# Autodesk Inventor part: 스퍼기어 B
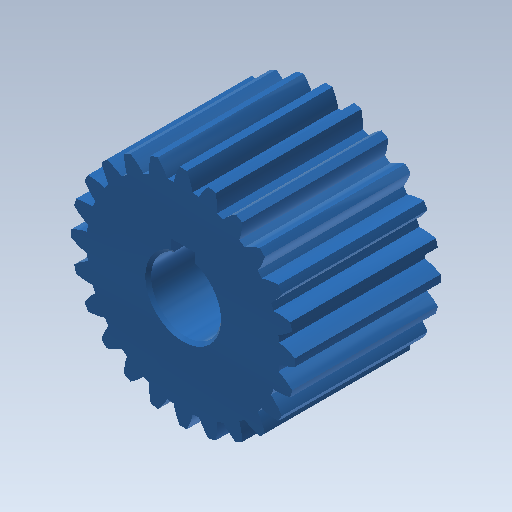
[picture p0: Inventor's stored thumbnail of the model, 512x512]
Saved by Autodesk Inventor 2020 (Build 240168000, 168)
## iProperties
CustomPartVersion: 1
Created: 2020-04
Part Number: 스퍼기어 B
Material: 강철, 연강
Document SubType Name: Modeling
Designer: mduedu
Categories: <?xml version="1.0" encoding="UTF-16"?> <MemberInstance><Categories><FamilyTemplate><FamilyTemplateParameter ValueType="xs:double" Id="1" ObjectReferenceKey="da
Density: 7.86 g/cm^3
Mass: 175.416 g
Surface Area: 76.8935 cm^2
Volume: 22.3176 cm^3
Appearance: 청록색
Author: mduedu
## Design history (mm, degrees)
sketch "Sketch1"
  geometry: C1 r 19.2 at (0, 0)
  constraints: 1 centre point
  dimensions: "d0" = 38.4 diameter of C1 (= da_da)
extrude "Extrusion1" new body sketch "Sketch1" distance "d1" = 25 (= da_b); taper "d2" = 0 deg
workplane "Work Plane2"
sketch "Sketch2"
  geometry: C1 r 19.2 at (0, 0) reference; C2 r 18 at (0, 0)
  constraints: 1 centre point, 1 coincident
  dimensions: "d3" = 36 diameter of C2 (= da_dw)
feature "피치 지름" sketch "Sketch2" dims "d4" = 10, "d5" = 0
workplane "Work Plane8"
workplane "Work Plane9"
feature "스퍼 기어" dims "da_b" = 25, "da_d" = 36, "da_aw" = 45, "da_da" = 38.4, "da_df" = 33.129, "da_dw" = 36, angle "da_beta" = 0 deg, "da_lefttooth" = 0, "da_righttooth" = 0
sketch "스케치3"
  geometry: L1 (-2, 5.657)-(2, 5.657); L2 (2, 5.657)-(2, 7.8); L3 (2, 7.8)-(-2, 7.8); L4 (-2, 7.8)-(-2, 5.657); A1 r 6 centre (0, 0) between (-2, 5.657) and (2, 5.657); 1 further point
  constraints: 8 end point, 2 parallel, 2 point on circle, 1 centre point, 1 coincident, 1 horizontal, 1 perpendicular
  dimensions: "d49" = 12 diameter of A1; "d51" = 4 distance of L2.end L3.end; "d52" = 13.8 dimension on A1 L3
extrude "돌출2" cut sketch "스케치3" extent not by distance; stored distance "d53" = 10; taper "d54" = 0 deg
chamfer "모따기1" distance "d55" = 0.5; stored, may be unused: second distance "d56" = 2, angle "d57" = 45 deg
body "Solid1"
body "Srf1"
other parameters: "d16" = 45 (= da_aw), "d17" = 0, "d34" = 7.5 deg (computed from da_z), "d39" = 0, "d41" = 0, "d43" = 45 (= da_aw), "d46" = 45 (= da_aw), "d47" = 0, "d48" = 0
